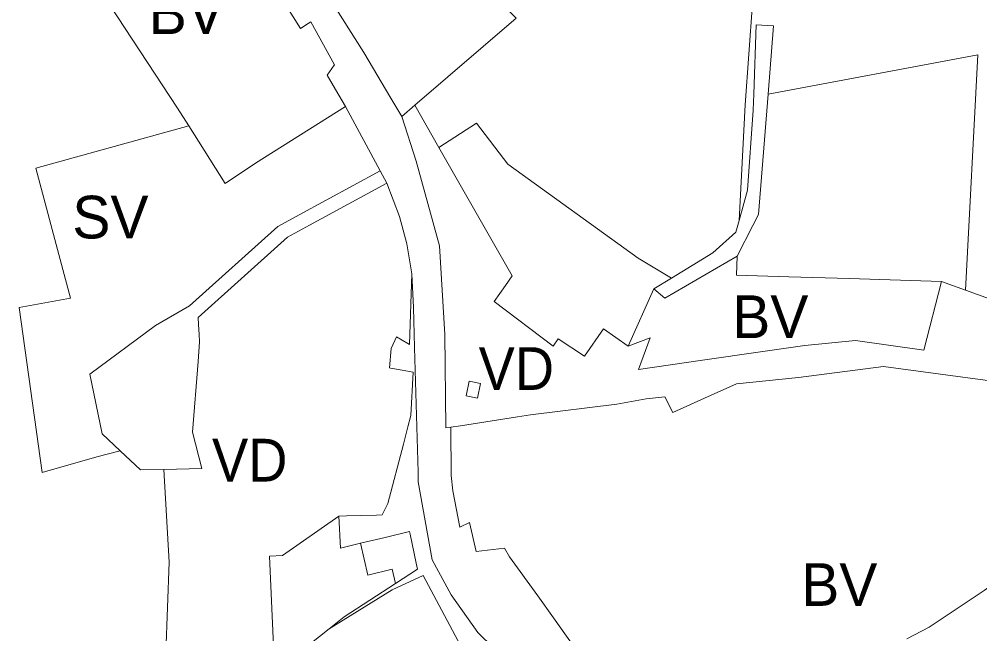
# Model space of a CAD drawing. Extents: x -650451 to -642268, y -1075216 to -1066610.
# Drawn here: x -645095 to -644825.3, y -1073048.7 to -1072876 of the extents above; entities that cross this region are included whole.
import ezdxf

# ---------------------------------------------------------------- set-up
doc = ezdxf.new("R2010")
doc.units = 0
doc.header["$LTSCALE"] = 4.8
for name, color, linetype, lineweight in [('11', 7, 'Continuous', 13), ('15', 7, 'Continuous', 13), ('19', 7, 'Continuous', 13), ('24', 7, 'Continuous', 13), ('3', 7, 'Continuous', 13), ('35', 7, 'Continuous', 13), ('45', 7, 'Continuous', 13), ('46', 7, 'Continuous', 13)]:
    doc.layers.add(name, color=color, linetype=linetype, lineweight=lineweight)
doc.layers.add('62', color=7, linetype='Continuous')

msp = doc.modelspace()

# ---------------------------------------------------------------- linework, layer by layer
at = {"layer": '11'}
msp.add_lwpolyline([(-644966.3, -1072982.52), (-644969.52, -1072981.84), (-644968.65, -1072977.73), (-644965.48, -1072978.36)], close=True, dxfattribs=at)
at = {"layer": '15'}
for points in [[(-644987.58, -1072903.38), (-644983.93, -1072900.24), (-644977.16, -1072912.11)], [(-644973.78, -1072990.67), (-644975.26, -1072990.9), (-644975.5, -1072964.62), (-644976.98, -1072939.7), (-644983.58, -1072915.92), (-644987.58, -1072903.38)], [(-644977.16, -1072912.11), (-644956.61, -1072948.16), (-644958.49, -1072950.87), (-644961.62, -1072955.39), (-644945.06, -1072967.89), (-644943.65, -1072965.85), (-644936.25, -1072970.76), (-644930.9, -1072963.08), (-644924, -1072967.87)], [(-645066.66, -1072997.3), (-645071.72, -1072992.52), (-645075.22, -1072975.8), (-645056.81, -1072962.13), (-645047.23, -1072956.57), (-645022.4, -1072934.31), (-645016.37, -1072931.01), (-644993.68, -1072918.61), (-644991.77, -1072922.13)], [(-644991.77, -1072922.13), (-645013.51, -1072933.92), (-645019.73, -1072937.29), (-645044.77, -1072959.83), (-645044.68, -1072961.82), (-645044.54, -1072964.66), (-645044.44, -1072966.73), (-645044.8, -1072972.22), (-645046.36, -1072992.1), (-645043.77, -1073002.3), (-645054.44, -1073002.54)], [(-645005.31, -1073015.68), (-645003.08, -1073015.61), (-644994.67, -1073015.36), (-644993.15, -1073015.31), (-644991.51, -1073012.16), (-644987.13, -1072995.44), (-644985.86, -1072990.55), (-644985.02, -1072987.36), (-644984.44, -1072975.19), (-644984.98, -1072975.1), (-644986.95, -1072974.75), (-644990.81, -1072974.08), (-644991.01, -1072974.02), (-644990.62, -1072968.58), (-644989.11, -1072965.25), (-644985.85, -1072967.18), (-644985.43, -1072967.43), (-644984.73, -1072947.56)], [(-644984.73, -1072947.56), (-644984.31, -1072957.08), (-644984, -1072968.31), (-644983.04, -1073003.33), (-644982.96, -1073006.06), (-644979.09, -1073027.97), (-644973.73, -1073037.82), (-644966.21, -1073048.32), (-644925.03, -1073088.75), (-644912.99, -1073104.65)], [(-644924, -1072967.87), (-644917.86, -1072965.55), (-644921.14, -1072974.47), (-644903.12, -1072971.8), (-644886.87, -1072969.46), (-644874.37, -1072967.75), (-644860.15, -1072966.28), (-644841.02, -1072969.02), (-644835.99, -1072949.74), (-644829.3, -1072952.16)], [(-644829.3, -1072952.16), (-644781.05, -1072969.61), (-644740.95, -1072987.23), (-644666.64, -1073051.97), (-644614.48, -1073096.25), (-644529.95, -1073158.06)], [(-644816.11, -1072978.51), (-644842.54, -1072974.93), (-644852.26, -1072973.62), (-644876.19, -1072976.67), (-644893.57, -1072978.46), (-644902.55, -1072982.55), (-644911.43, -1072986.59), (-644913.69, -1072982.13), (-644918.97, -1072982.7), (-644927.21, -1072984.16), (-644951.46, -1072987.25), (-644955.05, -1072987.8), (-644971.09, -1072990.31), (-644973.78, -1072990.67)], [(-645054.44, -1073002.54), (-645060.95, -1073002.68), (-645066.66, -1072997.3)], [(-644999.23, -1073023.29), (-645004.82, -1073024.63), (-645005.31, -1073015.68)], [(-644989.34, -1073034.58), (-644983.16, -1073030.56), (-644983.51, -1073028.9), (-644985.25, -1073020.72), (-644985.41, -1073019.98), (-644992.27, -1073021.63), (-644999.23, -1073023.29)], [(-644969.56, -1073058.48), (-644968.86, -1073057.45), (-644968.89, -1073056.23), (-644981.57, -1073032.3), (-644990.29, -1073036.36), (-645007.99, -1073047.31)], [(-645007.99, -1073047.31), (-645003.78, -1073043.96), (-644989.34, -1073034.58)]]:
    msp.add_lwpolyline(points, dxfattribs=at)
msp.add_lwpolyline([(-644966.3, -1072982.52), (-644965.48, -1072978.36), (-644968.65, -1072977.73), (-644969.52, -1072981.84)], close=True, dxfattribs=at)
at = {"layer": '19'}
msp.add_line((-645015.71, -1073053.41), (-645007.99, -1073047.31), dxfattribs=at)
for points in [[(-645047.42, -1072906.05), (-645037.2, -1072922.24), (-645028.68, -1072916.54), (-645003.44, -1072900.56), (-644993.68, -1072918.61)], [(-645088.62, -1073003.45), (-645095.04, -1072957.07), (-645080.61, -1072954.43), (-645083.13, -1072944.94), (-645090.34, -1072917.86), (-645047.42, -1072906.05)], [(-644993.68, -1072918.61), (-645016.37, -1072931.01), (-645022.4, -1072934.31), (-645047.23, -1072956.57), (-645056.81, -1072962.13), (-645075.22, -1072975.8), (-645071.72, -1072992.52), (-645066.66, -1072997.3)], [(-645066.66, -1072997.3), (-645073.23, -1072999.05), (-645088.62, -1073003.45)], [(-644999.23, -1073023.29), (-644992.27, -1073021.63), (-644985.41, -1073019.98), (-644985.25, -1073020.72), (-644983.51, -1073028.9), (-644983.16, -1073030.56), (-644989.34, -1073034.58)], [(-644989.34, -1073034.58), (-644990.25, -1073030.54), (-644997.09, -1073032.21), (-644999.23, -1073023.29)], [(-645007.99, -1073047.31), (-644990.29, -1073036.36), (-644981.57, -1073032.3), (-644968.89, -1073056.23), (-644968.86, -1073057.45), (-644969.56, -1073058.48)]]:
    msp.add_lwpolyline(points, dxfattribs=at)
at = {"layer": '24'}
for points in [[(-645003.44, -1072900.56), (-645006.19, -1072895.8), (-645008.52, -1072891.76), (-645006.58, -1072889), (-645006.5, -1072888.88), (-645013.11, -1072876.8), (-645013.89, -1072877.29), (-645016.06, -1072878.67), (-645027.47, -1072860.37), (-645035.06, -1072848.67), (-645039.21, -1072842.26), (-645055.76, -1072816.4)], [(-645007.8, -1072870.27), (-644998.3, -1072885.43), (-644990.66, -1072898.22), (-644987.58, -1072903.38)], [(-644984.73, -1072947.56), (-644986.2, -1072939.16), (-644988.28, -1072931.51), (-644991.77, -1072922.13), (-644993.68, -1072918.61), (-645003.44, -1072900.56)], [(-644987.58, -1072903.38), (-644983.58, -1072915.92), (-644976.98, -1072939.7), (-644975.5, -1072964.62), (-644975.26, -1072990.9), (-644973.78, -1072990.67)], [(-644912.99, -1073104.65), (-644925.03, -1073088.75), (-644966.21, -1073048.32), (-644973.73, -1073037.82), (-644979.09, -1073027.97), (-644982.96, -1073006.06), (-644983.04, -1073003.33), (-644984, -1072968.31), (-644984.31, -1072957.08), (-644984.73, -1072947.56)], [(-644973.78, -1072990.67), (-644973.77, -1073004.25), (-644973.27, -1073008.52), (-644971.33, -1073018.81), (-644968.59, -1073017.44), (-644966.71, -1073025.57), (-644958.75, -1073024.7), (-644957.31, -1073027.07), (-644949.4, -1073038.05), (-644944.96, -1073044.2), (-644932.48, -1073061.9), (-644927.92, -1073066.94), (-644918.82, -1073077.02), (-644912.36, -1073084.42)]]:
    msp.add_lwpolyline(points, dxfattribs=at)
at = {"layer": '3'}
msp.add_line((-644924, -1072967.87), (-644916.82, -1072951.76), dxfattribs=at)
for points in [[(-644940.8, -1072781.48), (-644920.46, -1072792.92), (-644945.2, -1072826.3), (-644959.24, -1072844.92), (-644972.28, -1072859.02), (-644969.93, -1072861.43), (-644955.49, -1072875.78), (-644983.93, -1072900.24), (-644987.58, -1072903.38)], [(-645055.76, -1072816.4), (-645039.21, -1072842.26), (-645035.06, -1072848.67), (-645027.47, -1072860.37), (-645016.06, -1072878.67), (-645013.89, -1072877.29), (-645013.11, -1072876.8), (-645006.5, -1072888.88), (-645006.58, -1072889), (-645008.52, -1072891.76), (-645006.19, -1072895.8), (-645003.44, -1072900.56)], [(-645047.42, -1072906.05), (-645050.6, -1072901.03), (-645069.55, -1072872.12), (-645079.81, -1072855.89), (-645084.47, -1072825.67)], [(-644987.58, -1072903.38), (-644990.66, -1072898.22), (-644998.3, -1072885.43), (-645007.8, -1072870.27)], [(-645003.44, -1072900.56), (-645028.68, -1072916.54), (-645037.2, -1072922.24), (-645047.42, -1072906.05)], [(-644916.82, -1072951.76), (-644913.74, -1072954.38), (-644893.37, -1072942.61)], [(-644893.37, -1072942.61), (-644893.59, -1072947.97), (-644878.86, -1072948.42), (-644861.93, -1072948.94), (-644835.99, -1072949.74)], [(-644835.99, -1072949.74), (-644841.02, -1072969.02), (-644860.15, -1072966.28), (-644874.37, -1072967.75), (-644886.87, -1072969.46), (-644903.12, -1072971.8), (-644921.14, -1072974.47), (-644917.86, -1072965.55), (-644924, -1072967.87)], [(-644973.78, -1072990.67), (-644971.09, -1072990.31), (-644955.05, -1072987.8), (-644951.46, -1072987.25), (-644927.21, -1072984.16), (-644918.97, -1072982.7), (-644913.69, -1072982.13), (-644911.43, -1072986.59), (-644902.55, -1072982.55), (-644893.57, -1072978.46), (-644876.19, -1072976.67), (-644852.26, -1072973.62), (-644842.54, -1072974.93), (-644816.11, -1072978.51)], [(-644912.36, -1073084.42), (-644918.82, -1073077.02), (-644927.92, -1073066.94), (-644932.48, -1073061.9), (-644944.96, -1073044.2), (-644949.4, -1073038.05), (-644957.31, -1073027.07), (-644958.75, -1073024.7), (-644966.71, -1073025.57), (-644968.59, -1073017.44), (-644971.33, -1073018.81), (-644973.27, -1073008.52), (-644973.77, -1073004.25), (-644973.78, -1072990.67)], [(-644745.73, -1073008.64), (-644748.95, -1073015.64), (-644757.73, -1073012.05), (-644764.69, -1073008.87), (-644778.38, -1073001.84), (-644781.52, -1073004.39), (-644801.54, -1073020.61), (-644824.08, -1073036.56), (-644832.7, -1073042.34), (-644839.47, -1073046.89), (-644845.72, -1073050.14)]]:
    msp.add_lwpolyline(points, dxfattribs=at)
at = {"layer": '35'}
for points in [[(-644977.16, -1072912.11), (-644966.57, -1072905.23), (-644957.79, -1072916.73), (-644921.18, -1072943.17), (-644911.87, -1072948.76), (-644916.82, -1072951.76), (-644924, -1072967.87)], [(-644924, -1072967.87), (-644930.9, -1072963.08), (-644936.25, -1072970.76), (-644943.65, -1072965.85), (-644945.06, -1072967.89), (-644961.62, -1072955.39), (-644958.49, -1072950.87), (-644956.61, -1072948.16), (-644977.16, -1072912.11)], [(-645054.44, -1073002.54), (-645043.77, -1073002.3), (-645046.36, -1072992.1), (-645044.8, -1072972.22), (-645044.44, -1072966.73), (-645044.54, -1072964.66), (-645044.68, -1072961.82), (-645044.77, -1072959.83), (-645019.73, -1072937.29), (-645013.51, -1072933.92), (-644991.77, -1072922.13)], [(-644991.77, -1072922.13), (-644988.28, -1072931.51), (-644986.2, -1072939.16), (-644984.73, -1072947.56)], [(-644984.73, -1072947.56), (-644985.43, -1072967.43), (-644985.85, -1072967.18), (-644989.11, -1072965.25), (-644990.62, -1072968.58), (-644991.01, -1072974.02), (-644990.81, -1072974.08), (-644986.95, -1072974.75), (-644984.98, -1072975.1), (-644984.44, -1072975.19), (-644985.02, -1072987.36), (-644985.86, -1072990.55), (-644987.13, -1072995.44), (-644991.51, -1073012.16), (-644993.15, -1073015.31), (-644994.67, -1073015.36), (-645003.08, -1073015.61), (-645005.31, -1073015.68)], [(-645060.1, -1073131.68), (-645053.83, -1073054.04), (-645052.94, -1073028.58), (-645054.44, -1073002.54)], [(-645005.31, -1073015.68), (-645021.1, -1073026.69), (-645024.71, -1073026.95), (-645023.6, -1073052.12)]]:
    msp.add_lwpolyline(points, dxfattribs=at)
at = {"layer": '45'}
msp.add_line((-644916.82, -1072951.76), (-644911.87, -1072948.76), dxfattribs=at)
for points in [[(-644892.86, -1072932.6), (-644890.48, -1072924.04), (-644888.92, -1072901.64), (-644888.76, -1072897.07), (-644888.06, -1072877.6), (-644883.16, -1072877.92), (-644884.712, -1072897.147)], [(-644884.712, -1072897.147), (-644887.44, -1072930.94), (-644888.99, -1072934), (-644893.37, -1072942.61)], [(-644911.87, -1072948.76), (-644900.2, -1072941.67), (-644893.77, -1072935.88), (-644892.86, -1072932.6)], [(-644893.37, -1072942.61), (-644913.74, -1072954.38), (-644916.82, -1072951.76)]]:
    msp.add_lwpolyline(points, dxfattribs=at)
at = {"layer": '46'}
for points in [[(-644892.86, -1072932.6), (-644891.2, -1072900.09), (-644889.11, -1072871.66), (-644902.18, -1072797.88), (-644901.35, -1072785.36), (-644898.29, -1072766.55), (-644899.2, -1072762.14)], [(-644884.712, -1072897.147), (-644883.16, -1072877.92), (-644888.06, -1072877.6), (-644888.76, -1072897.07), (-644888.92, -1072901.64), (-644890.48, -1072924.04), (-644892.86, -1072932.6)], [(-644829.3, -1072952.16), (-644825.855, -1072886.074), (-644884.712, -1072897.147)], [(-644529.95, -1073158.06), (-644614.48, -1073096.25), (-644666.64, -1073051.97), (-644740.95, -1072987.23), (-644781.05, -1072969.61), (-644829.3, -1072952.16)]]:
    msp.add_lwpolyline(points, dxfattribs=at)

# ---------------------------------------------------------------- texts
at = {"layer": '62'}
for s, p in [('BV', (-645058.673, -1072880.24)), ('SV', (-645080.125, -1072937.645)), ('BV', (-644894.803, -1072965.637)), ('BV', (-644875.421, -1073040.886))]:
    msp.add_text(s, height=12, dxfattribs=at).set_placement(p)
at = {"layer": '62', "width": 0.95}
for p in [(-644966.013, -1072980.198), (-645040.892, -1073005.939)]:
    msp.add_text('VD', height=12, dxfattribs=at).set_placement(p)

doc.saveas('drawing.dxf')
